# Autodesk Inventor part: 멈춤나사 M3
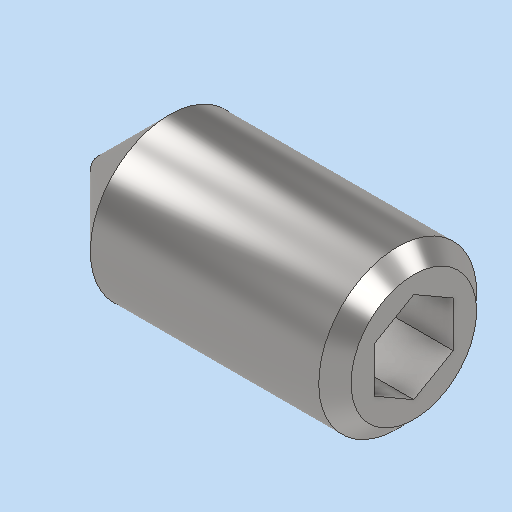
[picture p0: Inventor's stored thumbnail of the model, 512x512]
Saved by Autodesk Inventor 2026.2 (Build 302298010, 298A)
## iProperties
Created: 2026-08
Part Number: 멈춤나사 M3
Material: 강철, 연강
Description: 6각 소켓 머리 없는 멈춤 나사
Document SubType Name: Modeling
Designer: PC-2-06
Density: 7.85 g/cm^3
Appearance: 기본값
Author: jhkim
Sending System: Autodesk Inventor 2027
Preprocessor: ST-DEVELOPER v20.1
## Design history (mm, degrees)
feature "Solid1"
node "솔리드1"
